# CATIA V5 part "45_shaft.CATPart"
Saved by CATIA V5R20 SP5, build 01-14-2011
Part number: 45_shaft
Bounding box of the stored display mesh (mm): x -7.998 to 7.998, y 132.388 to 148.336, z -173.5 to -104.5
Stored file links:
  C:\Documents and Settings\anizard\Bureau\13\45_shaft.CATPart
  C:\Documents and Settings\anizard\Bureau\13\anizard.CATProduct
  C:\Program Files (x86)\Dassault Systemes\B20\intel_a\reffiles\standard\MetricThickPitch.txt
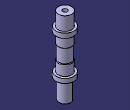
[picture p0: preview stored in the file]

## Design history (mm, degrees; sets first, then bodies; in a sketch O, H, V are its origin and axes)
Set1
  Plane1: linked copy from another document
  Line1: linked copy from another document
  Plane2 to Plane6: linked copy from another document
  Point1: linked copy from another document
  Point2: linked copy from another document
  Plane7 to Plane9: linked copy from another document
  Point3: linked copy from another document
  Point4: linked copy from another document
Body1 (main body)
  Sketch1 on Plane1, origin (0, 0, 0), H (0, 1, 0), V (0, 0, 1)
    line L1 (140.3619, -104.5) -> (146.3619, -104.5)
    line L2 (146.3619, -104.5) -> (146.3619, -116.5)
    line L3 (146.3619, -116.5) -> (148.3619, -116.5)
    line L4 (148.3619, -116.5) -> (148.3619, -120.5)
    line L5 (148.3619, -120.5) -> (146.3619, -120.5)
    line L6 (146.3619, -120.5) -> (146.3619, -129.5)
    point P7 (146.3619, -129.5)
    line L7 (146.3619, -129.5) -> (145.8619, -130)
    line L8 (145.8619, -130) -> (145.8619, -142)
    line L9 (145.8619, -142) -> (146.3619, -142.5)
    point P10 (146.3619, -142.5)
    line L10 (146.3619, -142.5) -> (146.3619, -151.5)
    line L11 (146.3619, -151.5) -> (148.3619, -151.5)
    line L12 (148.3619, -151.5) -> (148.3619, -155.5)
    line L13 (148.3619, -155.5) -> (145.3619, -155.5)
    line L14 (145.3619, -155.5) -> (145.3619, -173.5)
    line L15 (145.3619, -173.5) -> (140.3619, -173.5)
    line L16 (140.3619, -173.5) -> (140.3619, -104.5)
    reference projected line E1 (140.3619, -199.5) -> (140.3619, -79.5) from Line1
    reference intersected line E2 through (0, -128.5) direction (-1, 0) from Plane6
    reference projected point E3 (146.3619, -122.5) from Point1
    reference projected point E4 (145.3619, -155.5) from Point2
    reference intersected line E5 through (0, -174.5) direction (-1, 0) from Plane7
    reference intersected line E6 through (0, -155.5) direction (-1, 0) from Plane8
    reference intersected line E7 through (0, -151.5) direction (-1, 0) from Plane3
    reference intersected line E8 through (0, -103.5) direction (-1, 0) from Plane4
    reference intersected line E9 through (0, -116.5) direction (-1, 0) from Plane5
    reference intersected line E10 through (0, -120.5) direction (-1, 0) from Plane2
    reference intersected line E11 through (0, -143.5) direction (-1, 0) from Plane9
    distance L8 L6 = 0.5
    angle L7 L8 = 45
    angle L8 L9 = 45
    distance L12 L10 = 2
    distance L4 L6 = 2
    distance E2 P7 = 1
    distance L15 E5 = 1
    distance L1 E8 = 1
    distance P10 E11 = 1
    horizontal: L1 H, L3 H, L5 H, L11 H, L13 H, L15 H
    vertical: L2 V, L4 V, L6 V, L8 V, L10 V, L12 V, L14 V, L16 V
    coincidence: P10 L6, L16 E1, L2 L6, L6 E3, L14 E4, L13 E6, L11 E7, L3 E9, L5 E10
  Shaft1: profile Sketch1, axis Line1, angle 360
  Sketch2 on face of Shaft1 from Sketch1.L15, origin (0, 158, -173.5), H (1, 0, 0), V (0, -1, 0)
    point P1 (0, 17.6381)
    reference projected point E1 (0, 17.6381) from Point3
    coincidence: P1 E1
  Hole1: placed by Sketch2, at (0, 140.3619, -173.5) direction (0, 0, 1), diameter 4.134, depth 20, threaded "M5", thread diameter 5, thread depth 17, pitch 0.8
  Sketch3 on face of Shaft1 from Sketch1.L1, origin (0, 158, -104.5), H (1, 0, 0), V (0, 1, 0)
    point P1 (0, -17.6381)
    reference projected point E1 (0, -17.6381) from Point4
    coincidence: P1 E1
  Hole2: placed by Sketch3, at (0, 140.3619, -104.5) direction (0, 0, -1), diameter 4.134, depth 20, threaded "M5", thread diameter 5, thread depth 17, pitch 0.8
